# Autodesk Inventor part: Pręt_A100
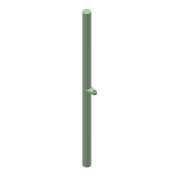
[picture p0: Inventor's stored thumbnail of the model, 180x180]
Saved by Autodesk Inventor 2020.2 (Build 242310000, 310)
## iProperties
Created: 2006-06
Part Number: Pręt_A100
Document SubType Name: Modeling
Designer: F.Stasiak
Density: 1 g/cm^3
Material: Ogólny
Appearance: Zielony pastelowy
Mass: 2064.4 g
Surface Area: 1725.68 cm^2
Volume: 2064.4 cm^3
Catalog Web Link: www.expertbooks.pl
Manager: www.cadconsulting.pl
Company: Fabian Stasiak CAD Consulting
Author: F.Stasiak
Subject: Zbiór ćwiczeń. Autodesk Inventor 2020. Kurs Professional
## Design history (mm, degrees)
sketch "Szkic1"
  geometry: C1 r 25 at (0, 0); 1 further point
  constraints: 1 centre point, 1 coincident
  dimensions: "d0" = 50 diameter of C1
extrude "Wyciągnięcie proste1" new body sketch "Szkic1" distance "d1" = 1040; taper "d2" = 0 deg
node "Płaszczyzna konstrukcyjna1"
sketch "Szkic2"
  geometry: L1 (-62.5, 14.79)-(-4.167, 24.65); L2 (-62.5, -14.79)-(-4.167, -24.65); L3 (-60, 0)-(0, 0); C1 r 10 at (-60, 0); A1 r 25 centre (0, 0) between (-4.167, 24.65) and (-4.167, -24.65) reference; A2 r 15 centre (-60, 0) between (-62.5, 14.79) and (-62.5, -14.79)
  constraints: 6 end point, 4 point on circle, 4 tangent, 2 centre point, 1 coincident, 1 horizontal
  dimensions: "d3" = 30 diameter of A2; "d4" = 60 distance of L3.end L3.start; "d7" = 20 diameter of C1
extrude "Wyciągnięcie proste2" join sketch "Szkic2" stored distance "d8" = 15; taper "d9" = 0 deg
node "Bryła1"
node "Korpusy bryłowe"
node "Korpusy powierzchniowe"
